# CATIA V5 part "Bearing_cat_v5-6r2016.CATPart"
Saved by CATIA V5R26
Part number: Bearing
Bounding box of the stored display mesh (mm): x -10 to 10, y -17.5 to 17.5, z -17.322 to 17.322
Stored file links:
  D:\_Deepak\CATIA\CATIA V5 2015 Parts Files\Tutorial Files\Tutorials\c16_catia_v5_6r2016_tut\Cam Follower mechanism\Bearing_cat_v5-6r2012.CATPart
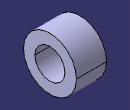
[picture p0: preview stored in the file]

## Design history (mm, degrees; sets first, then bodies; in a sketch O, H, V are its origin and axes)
Body1 (main body)
  Sketch1 on yz-plane, origin (0, 0, 0), H (0, 1, 0), V (0, 0, 1)
    circle A1 centre (0, 0) radius 10
    circle A2 centre (0, 0) radius 17.5
    radius A1 = 10
    radius A2 = 17.5
  Pad1: profile Sketch1, direction (1, 0, 0), length 10, mirrored extent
